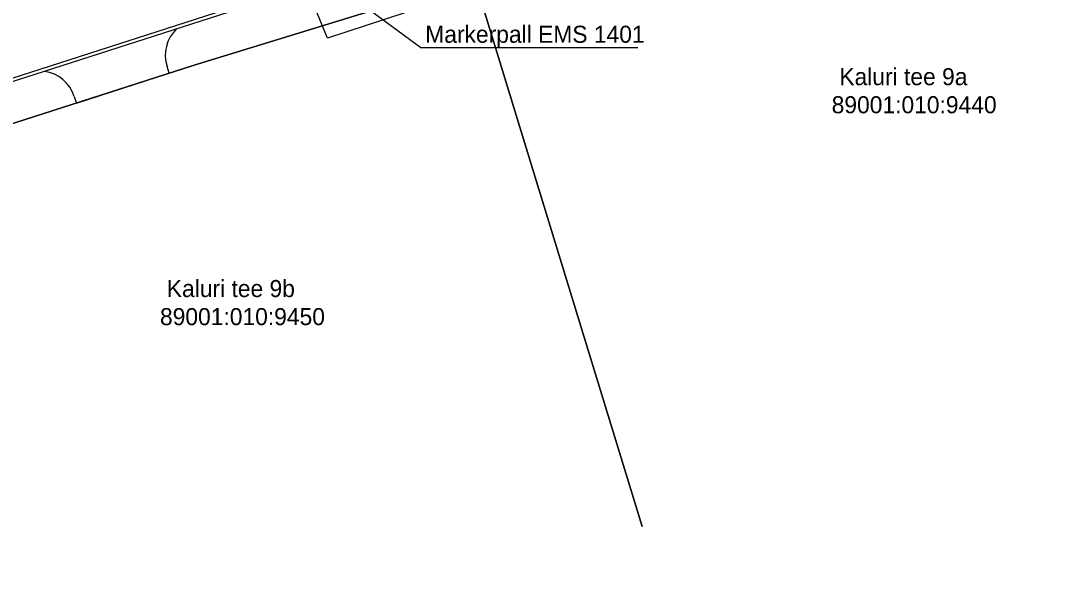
# Model space of a CAD drawing. Extents: x 546339 to 546593, y 6597108 to 6597251.
# Drawn here: x 546460.54 to 546503.11, y 6597155.92 to 6597179 of the extents above; entities that cross this region are included whole.
import ezdxf

# ---------------------------------------------------------------- set-up
doc = ezdxf.new("R2010")
doc.units = 0
for name, color, linetype in [('MOOTPIIR', 7, 'Continuous'), ('PIIR', 7, 'Continuous'), ('SITRASS', 7, 'Continuous'), ('TEE', 7, 'Continuous')]:
    doc.layers.add(name, color=color, linetype=linetype)

msp = doc.modelspace()

# ---------------------------------------------------------------- linework, layer by layer
at = {"layer": 'MOOTPIIR'}
msp.add_lwpolyline([(546510.398, 6597198.602), (546490.433, 6597192.051), (546491.122, 6597184.372), (546487.988, 6597183.494), (546485.449, 6597190.17), (546474.636, 6597186.911), (546476.297, 6597179.326), (546473.131, 6597178.291), (546470.279, 6597185.218), (546447.869, 6597177.79), (546448.872, 6597171.02), (546446.584, 6597170.142), (546443.888, 6597176.348), (546374.62, 6597155.63)], dxfattribs=at)
at = {"layer": 'PIIR'}
for points in [[(546339.379, 6597150.424), (546339.82, 6597150.4), (546343.3, 6597148.09), (546350.66, 6597143.2), (546387.61, 6597151.42), (546402.5, 6597155.95), (546434.27, 6597166.43), (546452.55, 6597172.32), (546467.66, 6597177.18), (546479.16, 6597180.72), (546505.65, 6597188.82)], [(546512.531, 6597166.376), (546505.65, 6597188.82), (546479.16, 6597180.72), (546486.042, 6597158.239)], [(546486.042, 6597158.239), (546479.16, 6597180.72), (546467.66, 6597177.18), (546452.55, 6597172.32), (546459.381, 6597150.05)]]:
    msp.add_lwpolyline(points, dxfattribs=at)
at = {"layer": 'SITRASS'}
msp.add_lwpolyline([(546474.423, 6597179.76), (546476.959, 6597177.904), (546485.856, 6597177.904)], dxfattribs=at)
at = {"layer": 'TEE'}
for p, q in [((546518.272, 6597195.197), (546396.577, 6597156.011)), ((546462.825, 6597175.625), (546466.633, 6597176.85)), ((546466.633, 6597176.85), (546466.545, 6597177.123)), ((546462.738, 6597175.897), (546462.825, 6597175.625))]:
    msp.add_line(p, q, dxfattribs=at)
msp.add_lwpolyline([(546396.531, 6597156.154), (546518.226, 6597195.34), (546518.226, 6597195.34)], dxfattribs=at)
for centre, start, end in [((546467.973, 6597177.582), 133.6906, 197.8487), ((546461.31, 6597175.437), 17.8487, 82.0068)]:
    msp.add_arc(centre, 1.5, start, end, dxfattribs=at)

# ---------------------------------------------------------------- texts
at = {"layer": 'PIIR'}
for s, p in [('Kaluri tee 9a', (546494.129, 6597176.357)), ('89001:010:9440', (546493.814, 6597175.204)), ('Kaluri tee 9b', (546466.537, 6597167.661)), ('89001:010:9450', (546466.257, 6597166.508))]:
    msp.add_text(s, height=0.7, dxfattribs=at).set_placement(p)
at = {"layer": 'SITRASS'}
msp.add_text('Markerpall EMS 1401', height=0.7, dxfattribs=at).set_placement((546477.14, 6597178.098))

doc.saveas('drawing.dxf')
